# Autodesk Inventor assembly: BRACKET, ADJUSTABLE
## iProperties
Title: BRACKET, ADJUSTABLE
Author: E. MOSS
Revision Number: C
Shininess: 50.0
PropertySet Name: _Private Model Information
Created: 2000-11
Part Number: BR101
Project: ACME
Description: BRACKET, AJUSTABLE
Document SubType Name: Assembly
Designer: J. DESIGNER
Control State: 0
Master: False
Checked Out: False
PropertySet Name: Design Tracking Control
Density: 0.0
Volumn: 0.0
Area: 0.0
PropertySet Name: Model Information
